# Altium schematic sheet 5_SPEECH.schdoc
size 124 x 99 mm
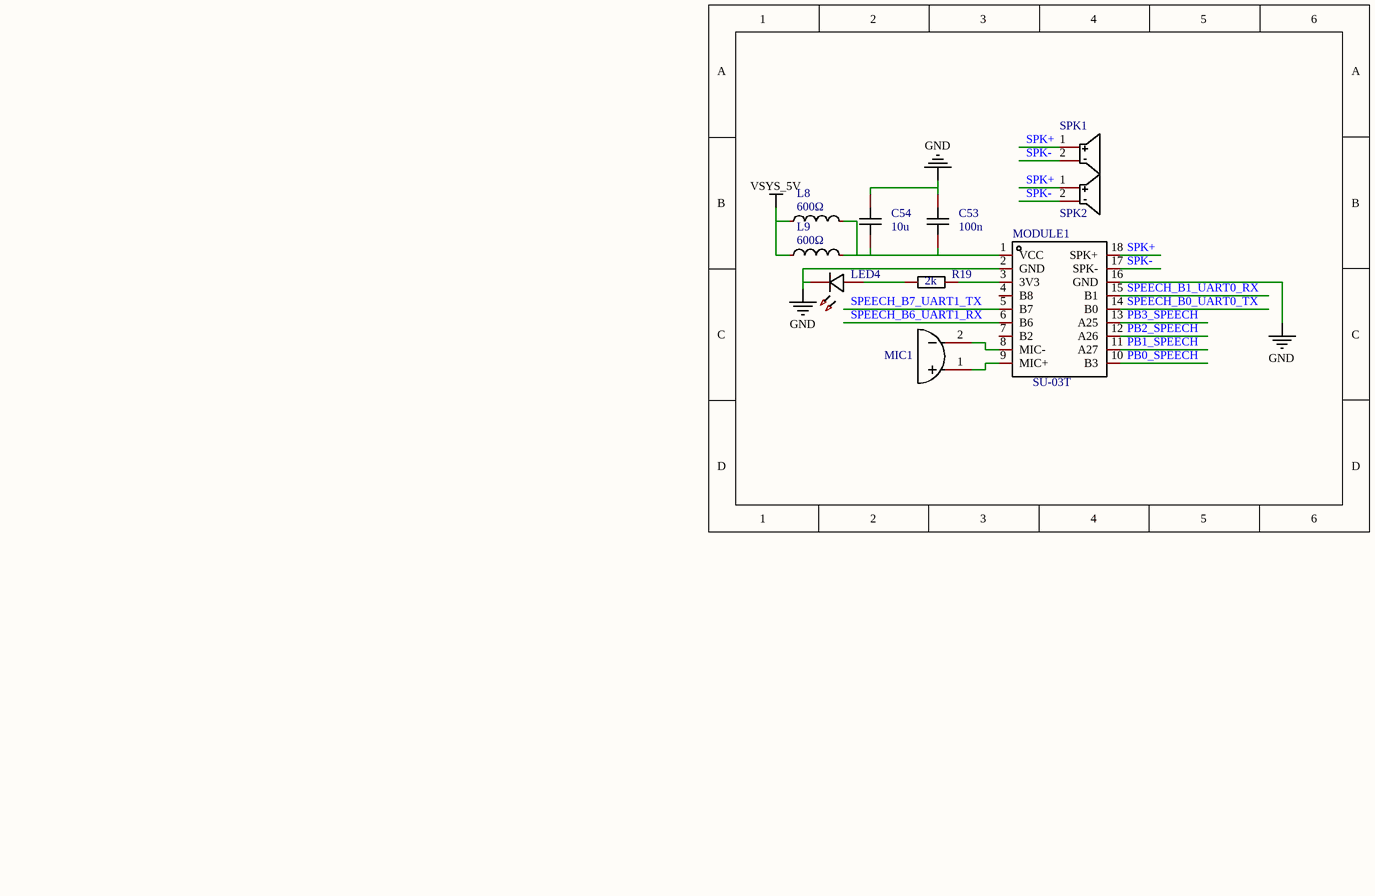
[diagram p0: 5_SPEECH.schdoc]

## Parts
C53  100n  [C0603]
C54  10u  [C0603]
L8  600Ω  [L0603]
L9  600Ω  [L0603]
LED4  LED_0603-G  [LED_0603]  (value not drawn)
MIC1  GMI6050P-60db  [MIC-TH_BD6.0-P1.90-D0.4-L-RD]  (value not drawn)
MODULE1  SU-03T  [COMM-SMD_18P-L21.0-W15.0-P2.00]
R19  2k  [R0603]
SPK1  FS-2308  [BEEP-TH_BD23.2-P9.20-D1.0]  (value not drawn)
SPK2  FS-2308  [BEEP-TH_BD23.2-P9.20-D1.0]  (value not drawn)

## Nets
GND: C53.1 C54.1 LED4.1(C) MODULE1.2(GND) MODULE1.16(GND)
VSYS_5V: L8.1 L9.1
PB0_SPEECH: MODULE1.10(B3)
PB1_SPEECH: MODULE1.11(A27)
PB2_SPEECH: MODULE1.12(A26)
PB3_SPEECH: MODULE1.13(A25)
SPEECH_B0_UART0_TX: MODULE1.14(B0)
SPEECH_B1_UART0_RX: MODULE1.15(B1)
SPEECH_B6_UART1_RX: MODULE1.6(B6)
SPEECH_B7_UART1_TX: MODULE1.5(B7)
SPK+: MODULE1.18(SPK+) SPK1.1 SPK2.1
SPK-: MODULE1.17(SPK-) SPK1.2 SPK2.2
NetC53_2: C53.2 C54.2 L8.2 L9.2 MODULE1.1(VCC)
NetLED4_2: LED4.2(A) R19.1
NetMIC1_1: MIC1.1 MODULE1.9(MIC+)
NetMIC1_2: MIC1.2 MODULE1.8(MIC-)
NetMODULE1_3: MODULE1.3(3V3) R19.2

Not connected (* = marked no-connect by the designer): MODULE1 4(B8) 7(B2)

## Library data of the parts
C53 C54 = CAP_0603: Symbol: CapAcitance; Convert to PCB: yes
L8 L9 = L_0603: Symbol: SDFL1608S100KTF; Add into BOM: yes
LED4 = LED_0603-G: Symbol: LED_G; Convert to PCB: yes
MIC1 = GMI6050P-60db: Manufacturer: INGHAi(赢海); Add into BOM: yes
MODULE1 = SU-03T: 处理器:-;运行内存:-;WIFI协议:-;蓝牙:-;以太网:-;USB:-;; Manufacturer: MACHINE INTELLIGENCE(机芯智能); Add into BOM: yes
R19 = Res_0603: Symbol: 电阻; Convert to PCB: yes
SPK1 SPK2 = FS-2308: Manufacturer: FUET(福声科技); Add into BOM: yes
